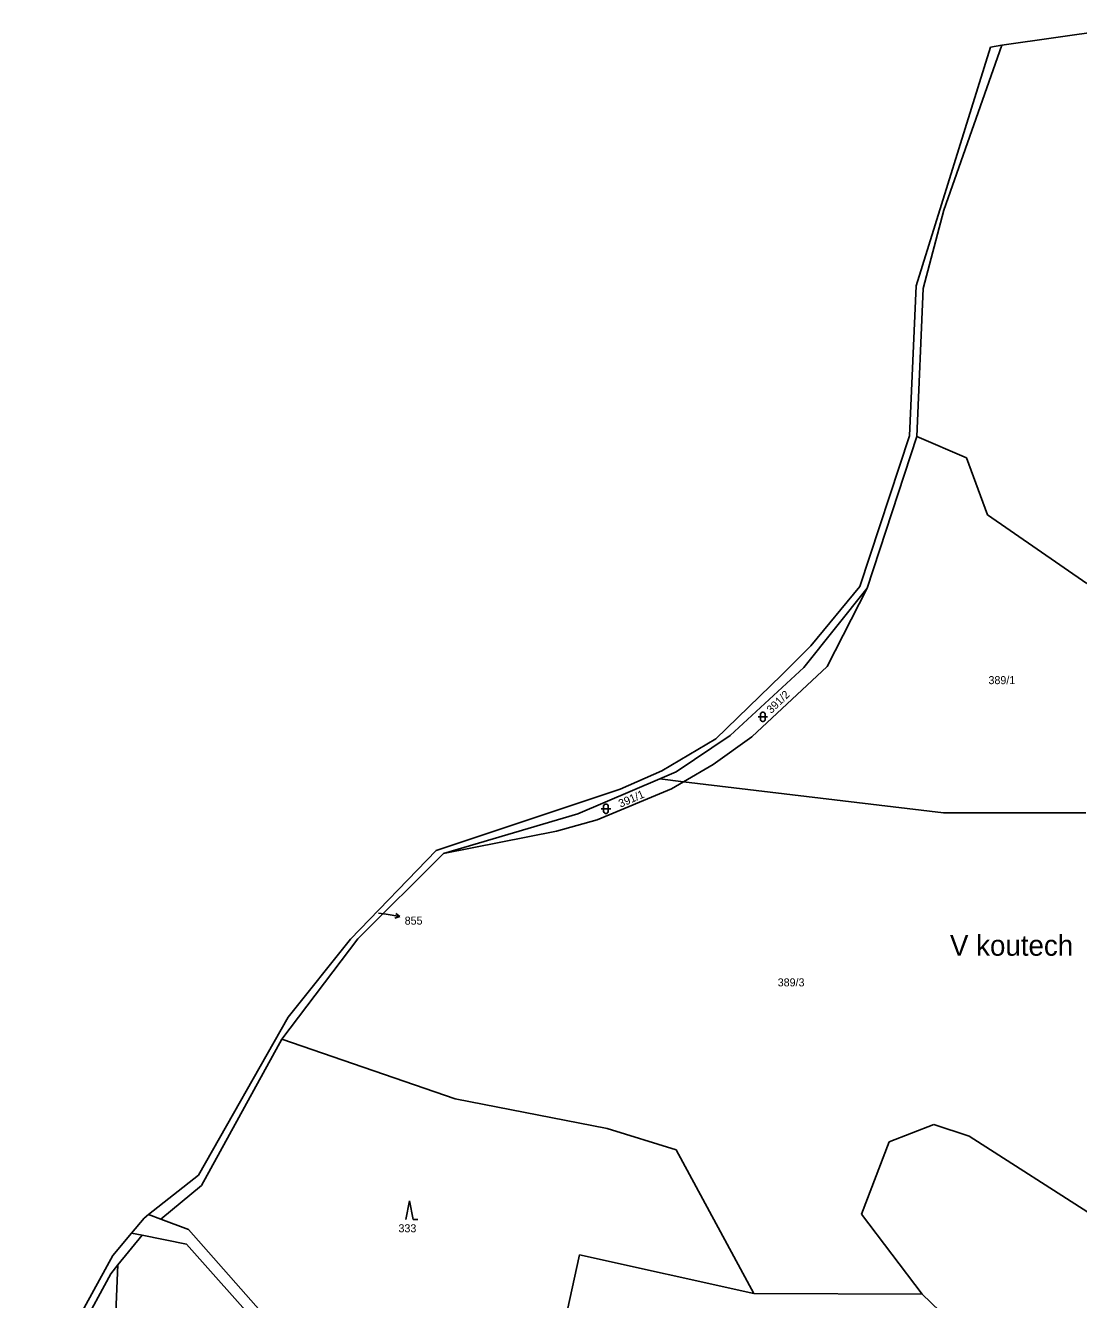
# Model space of a CAD drawing. Extents: x -791032 to -787751, y -1106872 to -1104403.
# Drawn here: x -790311.2 to -790087.5, y -1104694 to -1104423.3 of the extents above; entities that cross this region are included whole.
import ezdxf

# ---------------------------------------------------------------- set-up
doc = ezdxf.new("R2010")
doc.units = 0
for name, color, linetype in [('Komunikace', 7, 'Continuous'), ('Vrstva 1', 7, 'Continuous'), ('Vrstva 14', 7, 'Continuous'), ('Vrstva 16', 7, 'Continuous'), ('Vrstva 23', 7, 'Continuous'), ('Vrstva 39', 7, 'Continuous'), ('Vrstva 4', 7, 'Continuous')]:
    doc.layers.add(name, color=color, linetype=linetype)

msp = doc.modelspace()

# ---------------------------------------------------------------- linework, layer by layer
at = {"layer": 'Komunikace'}
msp.add_line((-790236.17, -1104611.86), (-790234.6, -1104612.12), dxfattribs=at)
at = {"layer": 'Vrstva 1'}
for p, q in [((-790116.08, -1104462.53), (-790103.82, -1104427.51)), ((-790120.5, -1104479.2), (-790116.08, -1104462.53)), ((-790121.85, -1104510.63), (-790120.5, -1104479.2)), ((-790132.42, -1104542.88), (-790121.85, -1104510.63)), ((-790121.85, -1104510.63), (-790111.32, -1104515.2)), ((-790111.32, -1104515.2), (-790106.85, -1104527.25)), ((-790106.85, -1104527.25), (-790085.74, -1104541.87)), ((-790145.88, -1104559.72), (-790132.42, -1104542.88)), ((-790140.91, -1104559.51), (-790132.42, -1104542.88)), ((-790161.52, -1104574.15), (-790145.88, -1104559.72)), ((-790156.92, -1104574.46), (-790140.91, -1104559.51)), ((-790172.98, -1104581.89), (-790161.52, -1104574.15)), ((-790165.09, -1104580.3), (-790156.92, -1104574.46)), ((-790176.45, -1104583.37), (-790172.98, -1104581.89)), ((-790171.43, -1104584), (-790165.09, -1104580.3)), ((-790193.84, -1104590.8), (-790176.45, -1104583.37)), ((-790189.76, -1104592.03), (-790173.99, -1104585.49)), ((-790176.45, -1104583.37), (-790171.43, -1104584)), ((-790173.99, -1104585.49), (-790171.43, -1104584)), ((-790171.43, -1104584), (-790116.21, -1104590.59)), ((-790222.41, -1104599.23), (-790193.84, -1104590.8)), ((-790116.21, -1104590.59), (-790085.98, -1104590.61)), ((-790198.37, -1104594.47), (-790189.76, -1104592.03)), ((-790222.41, -1104599.23), (-790198.37, -1104594.47)), ((-790240.62, -1104617.31), (-790222.41, -1104599.23)), ((-790256.72, -1104638.62), (-790240.62, -1104617.31)), ((-790273.82, -1104669.75), (-790256.72, -1104638.62)), ((-790256.72, -1104638.62), (-790219.9, -1104651.35)), ((-790219.9, -1104651.35), (-790187.63, -1104657.61)), ((-790187.63, -1104657.61), (-790173, -1104662.19)), ((-790118.21, -1104656.81), (-790127.7, -1104660.48)), ((-790110.73, -1104659.28), (-790118.21, -1104656.81)), ((-790127.7, -1104660.48), (-790133.58, -1104675.84)), ((-790083.73, -1104676.56), (-790110.73, -1104659.28)), ((-790173, -1104662.19), (-790156.49, -1104692.68)), ((-790282.43, -1104676.9), (-790273.82, -1104669.75)), ((-790282.43, -1104676.9), (-790285.06, -1104675.93)), ((-790276.56, -1104679.06), (-790282.43, -1104676.9)), ((-790133.58, -1104675.84), (-790120.69, -1104692.79)), ((-790291.54, -1104686.61), (-790286.38, -1104680.32)), ((-790286.38, -1104680.32), (-790288.65, -1104679.85)), ((-790277, -1104682.23), (-790286.38, -1104680.32)), ((-790276.56, -1104679.06), (-790257.34, -1104700.84)), ((-790277, -1104682.23), (-790259.61, -1104701.72)), ((-790193.51, -1104684.44), (-790196.64, -1104698.69)), ((-790156.49, -1104692.68), (-790193.51, -1104684.44)), ((-790305.37, -1104711.2), (-790293.08, -1104688.48)), ((-790295.12, -1104771.19), (-790291.54, -1104686.61)), ((-790293.08, -1104688.48), (-790291.54, -1104686.61)), ((-790156.49, -1104692.68), (-790120.69, -1104692.79)), ((-790120.69, -1104692.79), (-790103.79, -1104709.16))]:
    msp.add_line(p, q, dxfattribs=at)
at = {"layer": 'Vrstva 16'}
for p, q in [((-790234.6, -1104612.12), (-790231.641, -1104612.616)), ((-790231.641, -1104612.616), (-790232.71, -1104612.944)), ((-790231.641, -1104612.616), (-790232.544, -1104611.957))]:
    msp.add_line(p, q, dxfattribs=at)
at = {"layer": 'Vrstva 23'}
for p, q in [((-790155.06, -1104569.59), (-790154.96, -1104569.39)), ((-790154.96, -1104569.39), (-790154.86, -1104569.29)), ((-790154.86, -1104569.29), (-790154.66, -1104569.19)), ((-790154.66, -1104569.19), (-790154.46, -1104569.19)), ((-790154.46, -1104569.19), (-790154.26, -1104569.29)), ((-790154.26, -1104569.29), (-790154.16, -1104569.39)), ((-790154.16, -1104569.39), (-790154.06, -1104569.59)), ((-790155.56, -1104570.19), (-790153.56, -1104570.19)), ((-790155.06, -1104570.79), (-790155.06, -1104569.59)), ((-790154.96, -1104570.99), (-790155.06, -1104570.79)), ((-790154.86, -1104571.09), (-790154.96, -1104570.99)), ((-790154.66, -1104571.19), (-790154.86, -1104571.09)), ((-790154.46, -1104571.19), (-790154.66, -1104571.19)), ((-790154.26, -1104571.09), (-790154.46, -1104571.19)), ((-790154.16, -1104570.99), (-790154.26, -1104571.09)), ((-790154.06, -1104570.79), (-790154.16, -1104570.99)), ((-790154.06, -1104569.59), (-790154.06, -1104570.79)), ((-790188.88, -1104589.7), (-790186.88, -1104589.7)), ((-790188.38, -1104589.1), (-790188.28, -1104588.9)), ((-790188.38, -1104590.3), (-790188.38, -1104589.1)), ((-790188.28, -1104590.5), (-790188.38, -1104590.3)), ((-790188.28, -1104588.9), (-790188.18, -1104588.8)), ((-790188.18, -1104590.6), (-790188.28, -1104590.5)), ((-790188.18, -1104588.8), (-790187.98, -1104588.7)), ((-790187.98, -1104590.7), (-790188.18, -1104590.6)), ((-790187.98, -1104588.7), (-790187.78, -1104588.7)), ((-790187.78, -1104590.7), (-790187.98, -1104590.7)), ((-790187.78, -1104588.7), (-790187.58, -1104588.8)), ((-790187.58, -1104590.6), (-790187.78, -1104590.7)), ((-790187.58, -1104588.8), (-790187.48, -1104588.9)), ((-790187.48, -1104590.5), (-790187.58, -1104590.6)), ((-790187.48, -1104588.9), (-790187.38, -1104589.1)), ((-790187.38, -1104590.3), (-790187.48, -1104590.5)), ((-790187.38, -1104589.1), (-790187.38, -1104590.3)), ((-790230.42, -1104676.97), (-790229.62, -1104672.97)), ((-790229.62, -1104672.97), (-790228.82, -1104676.97)), ((-790228.82, -1104676.97), (-790227.82, -1104676.97))]:
    msp.add_line(p, q, dxfattribs=at)
at = {"layer": 'Vrstva 4'}
for p, q in [((-790074.19, -1104423.33), (-790103.82, -1104427.51)), ((-790106.2, -1104427.94), (-790122.01, -1104478.63)), ((-790103.82, -1104427.51), (-790106.2, -1104427.94)), ((-790122.01, -1104478.63), (-790123.41, -1104510.51)), ((-790123.41, -1104510.51), (-790133.99, -1104542.48)), ((-790133.99, -1104542.48), (-790144.35, -1104555.13)), ((-790144.35, -1104555.13), (-790150.59, -1104561.33)), ((-790150.59, -1104561.33), (-790164.58, -1104574.83)), ((-790164.58, -1104574.83), (-790175.99, -1104581.65)), ((-790175.99, -1104581.65), (-790184.9, -1104585.56)), ((-790184.9, -1104585.56), (-790223.95, -1104598.57)), ((-790223.95, -1104598.57), (-790242.14, -1104617.39)), ((-790242.14, -1104617.39), (-790255.37, -1104633.95)), ((-790255.37, -1104633.95), (-790274.42, -1104667.52)), ((-790274.42, -1104667.52), (-790285.06, -1104675.93)), ((-790285.96, -1104676.64), (-790288.65, -1104679.85)), ((-790285.06, -1104675.93), (-790285.96, -1104676.64)), ((-790288.65, -1104679.85), (-790292.6, -1104684.57)), ((-790292.6, -1104684.57), (-790311.19, -1104718.26))]:
    msp.add_line(p, q, dxfattribs=at)

# ---------------------------------------------------------------- texts
at = {"layer": 'Vrstva 14'}
for s, height, p in [('389/1', 1.7, (-790106.633, -1104563.24)), ('855', 0.1, (-790236.302, -1104611.86)), ('389/3', 1.7, (-790151.4, -1104627.44)), ('333', 1.7, (-790231.957, -1104679.67))]:
    msp.add_text(s, height=height, dxfattribs=at).set_placement(p)
for s, rotation, p in [('391/2', 44.05347, (-790152.785, -1104569.599)), ('391/1', 23.3487, (-790184.788, -1104589.493))]:
    msp.add_text(s, height=1.7, rotation=rotation, dxfattribs=at).set_placement(p)
at = {"layer": 'Vrstva 16'}
msp.add_text('855', height=1.7, dxfattribs=at).set_placement((-790230.64, -1104614.32))
at = {"layer": 'Vrstva 39'}
msp.add_text('V koutech', height=4.4, dxfattribs=at).set_placement((-790114.81, -1104620.93))

doc.saveas('drawing.dxf')
